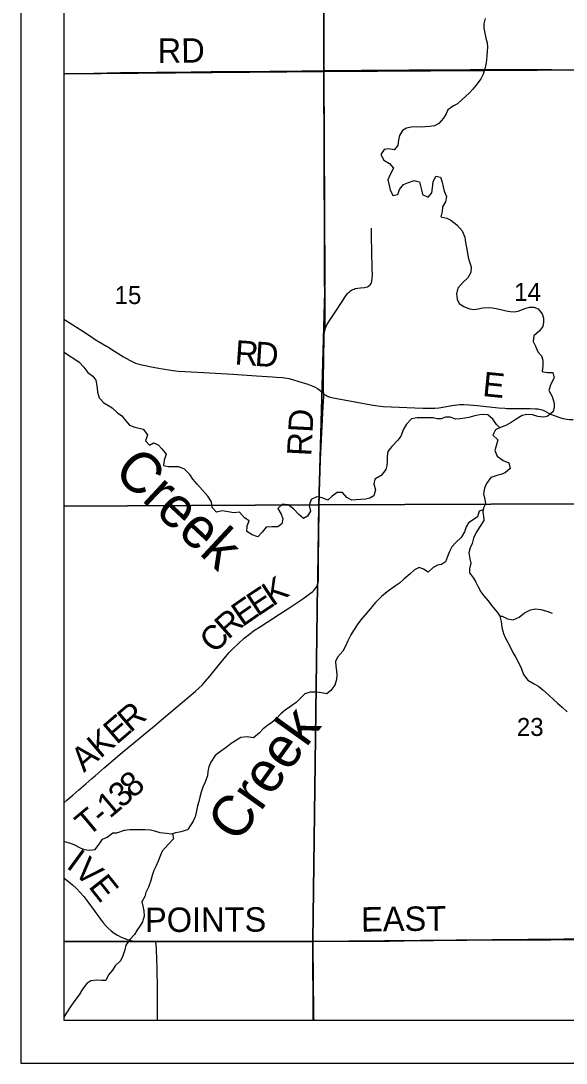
# Model space of a CAD drawing. Extents: x 0 to 70.2, y 0 to 31.4.
# Drawn here: x 2 to 3.272, y 14 to 16.429 of the extents above; entities that cross this region are included whole.
import ezdxf

# ---------------------------------------------------------------- set-up
doc = ezdxf.new("R2010")
doc.units = 0
for name, color, linetype in [('GM_X_County_Road', 7, 'Continuous'), ('GM_X_County_Road_Text', 7, 'Continuous'), ('GM_X_Minor_River', 7, 'Continuous'), ('GM_X_Minor_River_Text', 7, 'Continuous'), ('GM_X_Section', 7, 'Continuous'), ('GM_X_Section_Text', 7, 'Continuous'), ('GM_X_State_Route', 7, 'Continuous'), ('GM_X_Township_Road', 7, 'Continuous'), ('GM_X_Township_Road_Text', 7, 'Continuous'), ('SH_Cut_Line', 7, 'Continuous'), ('SH_Data', 7, 'Continuous')]:
    doc.layers.add(name, color=color, linetype=linetype)

msp = doc.modelspace()

# ---------------------------------------------------------------- linework, layer by layer
at = {"layer": 'GM_X_County_Road'}
for points in [[(2.1, 14.4319), (2.1013, 14.431), (2.1113, 14.4235), (2.1208, 14.4154), (2.1298, 14.4067), (2.1384, 14.3977), (2.1466, 14.3882), (2.1562, 14.3761), (2.1708, 14.3559), (2.1854, 14.3358), (2.193, 14.326), (2.1991, 14.319), (2.2034, 14.3146), (2.2103, 14.3085), (2.2178, 14.303), (2.2256, 14.2981), (2.2338, 14.2938), (2.2423, 14.2901), (2.2481, 14.288), (2.254, 14.2863), (2.26, 14.285), (2.2692, 14.2839), (2.2816, 14.2834), (2.3064, 14.2833), (2.3149, 14.2834)], [(2.3149, 14.2834), (2.3996, 14.2837), (2.4431, 14.2838), (2.5053, 14.2839), (2.5861, 14.2841), (2.6576, 14.2841), (2.6808, 14.2841)], [(2.6808, 14.2841), (2.7074, 14.284), (2.8316, 14.2843), (2.8596, 14.2845), (2.8938, 14.2851), (2.9622, 14.2854), (3.0399, 14.2868), (3.1021, 14.2871), (3.1736, 14.2876), (3.2356, 14.2872), (3.3133, 14.2878), (3.3941, 14.289), (3.4376, 14.2895), (3.4749, 14.2901), (3.4936, 14.2899), (3.5035, 14.2898)]]:
    msp.add_lwpolyline(points, dxfattribs=at)
at = {"layer": 'GM_X_Minor_River'}
for points in [[(3.0825, 16.434), (3.0795, 16.4218), (3.0795, 16.4116), (3.0821, 16.3998), (3.0844, 16.3884), (3.087, 16.3771), (3.0878, 16.3676), (3.0874, 16.3581), (3.0866, 16.3463), (3.0847, 16.3308), (3.0821, 16.3168), (3.0779, 16.3046), (3.0726, 16.2936), (3.0616, 16.2788), (3.054, 16.2693), (3.0453, 16.2599), (3.0293, 16.2454), (3.0183, 16.2356), (3.0085, 16.2303), (2.996, 16.2215), (2.9914, 16.2121), (2.9853, 16.2018), (2.9747, 16.1893), (2.9645, 16.184), (2.9527, 16.1821), (2.9425, 16.1817), (2.9319, 16.1809), (2.9217, 16.1813), (2.9099, 16.1809), (2.8993, 16.1783), (2.8898, 16.1734), (2.8826, 16.1616), (2.8807, 16.151), (2.8792, 16.1385), (2.8704, 16.1278), (2.8579, 16.1305), (2.8473, 16.1286), (2.8394, 16.1168), (2.8462, 16.1036), (2.8594, 16.096), (2.8693, 16.085), (2.8609, 16.0709), (2.856, 16.058), (2.8587, 16.0451), (2.8613, 16.0345), (2.867, 16.022), (2.8791, 16.0243), (2.8833, 16.0357), (2.892, 16.047), (2.9041, 16.052), (2.917, 16.0562), (2.9292, 16.0535), (2.9322, 16.044), (2.9345, 16.0345), (2.9364, 16.0239), (2.9496, 16.0175), (2.9583, 16.0277), (2.9599, 16.0398), (2.9618, 16.0535), (2.9678, 16.0668), (2.9788, 16.0641), (2.9826, 16.0527), (2.9849, 16.0417), (2.9872, 16.0319), (2.9925, 16.019), (2.9902, 16.0072), (2.983, 15.9951), (2.9822, 15.9845), (2.9792, 15.9716), (2.9932, 15.9685), (3.0027, 15.9644), (3.0163, 15.953), (3.0292, 15.939), (3.0349, 15.9249), (3.0371, 15.9124), (3.0394, 15.9003), (3.0413, 15.887), (3.0428, 15.8768), (3.047, 15.8646), (3.05, 15.8551), (3.0492, 15.8419), (3.042, 15.8297), (3.031, 15.8195), (3.0189, 15.8058), (3.0158, 15.7922), (3.017, 15.78), (3.0223, 15.7702), (3.0333, 15.763), (3.0465, 15.7577), (3.0568, 15.7561), (3.0666, 15.7577), (3.0772, 15.7596), (3.0905, 15.7603), (3.1, 15.7596), (3.1125, 15.7573), (3.122, 15.755), (3.1314, 15.7531), (3.1413, 15.7512), (3.1519, 15.7508), (3.1618, 15.7531)], [(3.1618, 15.7531), (3.1754, 15.7581), (3.186, 15.7618), (3.1959, 15.7615), (3.2065, 15.7577), (3.2156, 15.7463), (3.2186, 15.7361), (3.219, 15.7266), (3.2175, 15.7167), (3.2084, 15.7053), (3.1962, 15.6947), (3.1947, 15.6814), (3.2004, 15.6708), (3.2053, 15.6575), (3.214, 15.6481), (3.2174, 15.6378), (3.2174, 15.6245), (3.2159, 15.6117), (3.2273, 15.6094), (3.2402, 15.609), (3.2432, 15.5965), (3.2348, 15.5806), (3.231, 15.5673), (3.2386, 15.5532), (3.2439, 15.5381), (3.2439, 15.5282), (3.2409, 15.5187), (3.2291, 15.5073), (3.2196, 15.5051), (3.2052, 15.507), (3.1931, 15.5108), (3.1795, 15.5115), (3.1688, 15.5089), (3.1548, 15.5005), (3.1434, 15.4929), (3.1305, 15.4861), (3.1199, 15.4815), (3.1067, 15.4755), (3.1006, 15.4633), (3.112, 15.452), (3.1085, 15.4387), (3.1055, 15.4277), (3.1104, 15.4144), (3.1248, 15.4045), (3.1381, 15.3985), (3.1407, 15.3856), (3.1294, 15.3757), (3.1195, 15.3719), (3.11, 15.3696), (3.0956, 15.3647), (3.0854, 15.3507), (3.0812, 15.3397), (3.0785, 15.3268), (3.0819, 15.3131), (3.0835, 15.3033), (3.0789, 15.2938), (3.077, 15.2835), (3.0785, 15.2741), (3.0793, 15.2646), (3.0713, 15.2513), (3.0614, 15.2365), (3.0554, 15.2236), (3.0523, 15.2111), (3.0478, 15.2005), (3.0447, 15.1887), (3.0466, 15.1751), (3.0493, 15.1652), (3.0462, 15.1519), (3.0462, 15.1421), (3.0557, 15.1303), (3.061, 15.1204), (3.0655, 15.111), (3.0724, 15.0981), (3.0796, 15.0886), (3.0894, 15.0772), (3.0985, 15.0654), (3.111, 15.051), (3.1167, 15.0415), (3.1201, 15.0287), (3.1216, 15.0154), (3.1254, 15.0013), (3.1292, 14.9915), (3.1345, 14.9816), (3.142, 14.9687), (3.147, 14.957), (3.1538, 14.9452), (3.1614, 14.9319), (3.1674, 14.9187), (3.1723, 14.9054), (3.1822, 14.8925), (3.1966, 14.8842), (3.2076, 14.8773), (3.2174, 14.8701), (3.2303, 14.8584), (3.2417, 14.8477), (3.2515, 14.839), (3.2621, 14.8295), (3.2739, 14.8189)], [(2.1, 15.6563), (2.103, 15.6548), (2.1136, 15.6479), (2.1239, 15.6415), (2.136, 15.6335), (2.147, 15.6217), (2.1565, 15.6096), (2.1679, 15.6008), (2.1748, 15.5914), (2.1778, 15.5735), (2.1786, 15.5636), (2.1828, 15.5503), (2.1934, 15.5382), (2.2029, 15.5329), (2.2128, 15.5272), (2.2257, 15.515), (2.2356, 15.5082)], [(2.2356, 15.5082), (2.2443, 15.4972), (2.2534, 15.4862), (2.2656, 15.4816), (2.2758, 15.4797), (2.2853, 15.4771), (2.2956, 15.4641), (2.291, 15.4497), (2.3001, 15.4402), (2.3096, 15.4455), (2.3206, 15.441), (2.329, 15.4311), (2.3385, 15.4186), (2.3343, 15.4053), (2.3328, 15.3924), (2.3438, 15.3905), (2.3575, 15.3905), (2.3677, 15.3901), (2.381, 15.3844)], [(3.1168, 15.4801), (3.1093, 15.4884), (3.1006, 15.5005), (3.0892, 15.5104), (3.076, 15.5111), (3.0654, 15.5096), (3.0555, 15.5073), (3.0449, 15.5043), (3.0354, 15.5028), (3.0237, 15.5016), (3.0142, 15.5005), (3.0013, 15.505), (2.9903, 15.505), (2.9801, 15.5009), (2.9706, 15.5016), (2.9611, 15.5039), (2.9243, 15.5039), (2.9107, 15.5012), (2.8989, 15.4887), (2.8925, 15.477), (2.886, 15.461), (2.8788, 15.4512), (2.8648, 15.4367), (2.8561, 15.425), (2.8538, 15.4132), (2.8538, 15.4022), (2.853, 15.3924), (2.8507, 15.3829), (2.8401, 15.3696), (2.8257, 15.3605), (2.8234, 15.3499), (2.8268, 15.3358), (2.8234, 15.3222), (2.8139, 15.3165), (2.8045, 15.3142), (2.7931, 15.3135), (2.7813, 15.3123), (2.7719, 15.3116), (2.7601, 15.318), (2.7503, 15.3294), (2.7374, 15.3294), (2.7256, 15.321), (2.7161, 15.3116), (2.7029, 15.3169), (2.69, 15.3199), (2.6767, 15.3134), (2.6725, 15.2994), (2.6756, 15.2865), (2.6687, 15.2748), (2.6589, 15.2687), (2.6483, 15.2782), (2.6354, 15.2918), (2.6233, 15.3005), (2.6104, 15.3024), (2.5994, 15.2922), (2.6073, 15.2793), (2.6107, 15.2683), (2.6088, 15.2565), (2.599, 15.2493), (2.5849, 15.2493), (2.5717, 15.2489), (2.5626, 15.2372), (2.5523, 15.2266), (2.5394, 15.2311), (2.5266, 15.2391), (2.5277, 15.252), (2.5326, 15.2637), (2.5216, 15.2706), (2.5099, 15.2835), (2.4963, 15.2823), (2.4834, 15.2842), (2.4697, 15.2869), (2.4561, 15.2838), (2.4458, 15.2948), (2.4447, 15.3077), (2.4364, 15.321), (2.4239, 15.335), (2.4121, 15.3479), (2.4011, 15.3604), (2.3943, 15.3718), (2.381, 15.3844)], [(3.0781, 15.2896), (3.069, 15.2862), (3.0645, 15.2733), (3.0546, 15.2657), (3.0436, 15.2593), (3.0387, 15.2498), (3.0341, 15.238), (3.0269, 15.2251), (3.014, 15.2134), (3.0049, 15.2031), (2.9996, 15.1921), (2.9951, 15.1804), (2.9905, 15.1678), (2.981, 15.1618), (2.9716, 15.1602), (2.9617, 15.1546), (2.9499, 15.1443), (2.9386, 15.1511), (2.9291, 15.1549), (2.9177, 15.1492), (2.9079, 15.1405), (2.8931, 15.1276), (2.8828, 15.1181), (2.8733, 15.1121), (2.8544, 15.0984), (2.8411, 15.087), (2.8267, 15.073), (2.8153, 15.0597), (2.8024, 15.0438), (2.7929, 15.0328), (2.7842, 15.0214), (2.7755, 15.0081), (2.7698, 14.9983), (2.7626, 14.9838), (2.7569, 14.9713), (2.7508, 14.9603), (2.7391, 14.9471), (2.7338, 14.9364), (2.7345, 14.9251), (2.7364, 14.9144), (2.7368, 14.9042), (2.7364, 14.8943), (2.7318, 14.8807), (2.7231, 14.8682), (2.7136, 14.8609), (2.7007, 14.8625), (2.6898, 14.8644), (2.675, 14.8647), (2.6621, 14.8602), (2.6511, 14.8499), (2.642, 14.8401), (2.6291, 14.831), (2.6166, 14.8222), (2.6063, 14.8139), (2.595, 14.8025), (2.5855, 14.7938), (2.5752, 14.787), (2.5654, 14.779), (2.5566, 14.7695), (2.5426, 14.7581), (2.5275, 14.7604), (2.5127, 14.7589), (2.5028, 14.7528), (2.4903, 14.7445), (2.4789, 14.7357), (2.4653, 14.7263), (2.4535, 14.7168), (2.4433, 14.7016), (2.4387, 14.6902), (2.4364, 14.6796), (2.4349, 14.6694), (2.4292, 14.6531), (2.4243, 14.6428), (2.4205, 14.6314), (2.4175, 14.6197), (2.4152, 14.6094), (2.4121, 14.5999), (2.4099, 14.5882), (2.4061, 14.5738), (2.4019, 14.5635), (2.389, 14.5441)], [(3.1167, 15.0415), (3.1224, 15.0412), (3.1349, 15.0351), (3.1481, 15.0328), (3.1618, 15.0393), (3.1743, 15.0495), (3.1883, 15.0564), (3.1997, 15.0583), (3.2122, 15.0571), (3.2266, 15.0533), (3.2391, 15.0488)], [(2.1, 14.5165), (2.1012, 14.5163), (2.1157, 14.5125), (2.1251, 14.5087), (2.1384, 14.5015), (2.1479, 14.4977), (2.1608, 14.4965), (2.1734, 14.498), (2.184, 14.5125), (2.1904, 14.522), (2.2014, 14.5262), (2.2143, 14.5364), (2.2242, 14.5368), (2.2421, 14.5425), (2.2538, 14.5444), (2.2637, 14.5441), (2.2755, 14.5441), (2.2895, 14.5441), (2.3024, 14.5433), (2.3119, 14.541), (2.3244, 14.5376), (2.3396, 14.5357), (2.3514, 14.5346), (2.3617, 14.5376), (2.3738, 14.5399), (2.389, 14.5441)], [(2.354, 14.5354), (2.356, 14.5224), (2.3446, 14.5103), (2.3298, 14.4943), (2.326, 14.4848), (2.3199, 14.4704), (2.315, 14.4582), (2.3104, 14.4487), (2.3066, 14.4369), (2.3029, 14.4255), (2.2979, 14.41), (2.2911, 14.3978), (2.2888, 14.3883), (2.2824, 14.3758), (2.2847, 14.3655), (2.2869, 14.3549), (2.2873, 14.3424), (2.2839, 14.3291), (2.2778, 14.3192), (2.2703, 14.3089), (2.2649, 14.2994), (2.2539, 14.2884), (2.2448, 14.2751), (2.2422, 14.2641), (2.238, 14.2504), (2.2323, 14.2382), (2.2202, 14.2268), (2.2137, 14.217), (2.2046, 14.2059), (2.1982, 14.1926), (2.1879, 14.1923), (2.1765, 14.1934), (2.1636, 14.1915), (2.1541, 14.1854), (2.1439, 14.1725), (2.1363, 14.1592), (2.1238, 14.1428), (2.1147, 14.1307), (2.1052, 14.1151), (2.1, 14.1069)]]:
    msp.add_lwpolyline(points, dxfattribs=at)
at = {"layer": 'GM_X_Section'}
for points in [[(2.7039, 17.3191), (3.7116, 17.3342), (3.7004, 16.3169), (2.7071, 16.3105)], [(2.7071, 16.3105), (3.7004, 16.3169), (3.6966, 15.3051), (2.695, 15.3009), (2.7094, 15.8251)], [(3.6966, 15.3051), (3.6837, 14.2925), (2.681, 14.2838), (2.695, 15.3009)]]:
    msp.add_lwpolyline(points, close=True, dxfattribs=at)
at = {"layer": 'GM_X_Section_Text'}
for points in [[(2.1, 18.3126), (2.1, 14.1), (2.683, 14.1), (2.6825, 14.1062), (2.6824, 14.1385), (2.6819, 14.1739), (2.6818, 14.1969), (2.6815, 14.2211), (2.6812, 14.2482), (2.6806, 14.2846), (2.6914, 15.1151), (2.6923, 15.118), (2.6927, 15.1204), (2.693, 15.1229), (2.6931, 15.1295), (2.6935, 15.1758), (2.6943, 15.2286), (2.6948, 15.2908), (2.6958, 15.3311), (2.6983, 15.4057), (2.6993, 15.4368), (2.7032, 15.5143), (2.705, 15.5422), (2.7055, 15.5515), (2.7055, 15.5553), (2.7057, 15.5609), (2.7052, 15.5638), (2.7049, 15.5824), (2.7057, 15.6508), (2.7062, 15.6818), (2.7068, 15.6974), (2.7074, 15.7036), (2.7085, 15.7085), (2.7066, 16.3132), (2.7027, 17.7825)], [(2.7027, 17.7825), (2.7066, 16.3132), (2.7085, 15.7085), (2.7074, 15.7036), (2.7068, 15.6974), (2.7062, 15.6818), (2.7057, 15.6508), (2.7049, 15.5824), (2.7052, 15.5638), (2.7057, 15.5609), (2.7055, 15.5553), (2.7055, 15.5515), (2.705, 15.5422), (2.7032, 15.5143), (2.6993, 15.4368), (2.6983, 15.4057), (2.6958, 15.3311), (2.6948, 15.2908), (2.6943, 15.2286), (2.6935, 15.1758), (2.6931, 15.1295), (2.693, 15.1229), (2.6927, 15.1204), (2.6923, 15.118), (2.6914, 15.1151), (2.6806, 14.2846), (2.6812, 14.2482), (2.6815, 14.2211), (2.6818, 14.1969), (2.6819, 14.1739), (2.6824, 14.1385), (2.6825, 14.1062), (2.683, 14.1), (6.7623, 14.1)]]:
    msp.add_lwpolyline(points, dxfattribs=at)
at = {"layer": 'GM_X_State_Route'}
for points in [[(2.1, 17.3126), (2.1, 16.3054), (2.7071, 16.3105), (2.7039, 17.3191)], [(2.1, 16.3054), (2.1, 15.2974), (2.695, 15.3009), (2.7094, 15.8251), (2.7071, 16.3105)], [(2.1, 15.2974), (2.1, 14.2833), (2.681, 14.2838), (2.695, 15.3009)], [(2.1, 14.2833), (2.1, 14.1), (2.6814, 14.1), (2.681, 14.2838)], [(2.6814, 14.1), (3.6862, 14.1), (3.6837, 14.2925), (2.681, 14.2838)]]:
    msp.add_lwpolyline(points, close=True, dxfattribs=at)
at = {"layer": 'GM_X_Township_Road'}
msp.add_line((2.6554, 16.3121), (2.7068, 16.3127), dxfattribs=at)
for points in [[(2.1, 16.3055), (2.1024, 16.3055), (2.1388, 16.3062), (2.2324, 16.308), (2.2728, 16.3085), (2.3162, 16.3089), (2.397, 16.3095), (2.4436, 16.3102), (2.4715, 16.3104), (2.5802, 16.3113), (2.6051, 16.3115), (2.6554, 16.3121)], [(2.7068, 16.3127), (2.7169, 16.3128), (2.7945, 16.3133), (2.8314, 16.3136), (2.8625, 16.3138), (2.905, 16.3143), (2.9608, 16.3144), (3.0104, 16.3147), (3.0477, 16.3149), (3.1627, 16.3154), (3.2032, 16.3156), (3.238, 16.3151), (3.2654, 16.3147), (3.345, 16.314), (3.35, 16.3138), (3.3558, 16.3133), (3.363, 16.3114)], [(2.7087, 15.7079), (2.709, 15.7091), (2.7111, 15.7149), (2.7138, 15.7205), (2.7186, 15.7285), (2.7341, 15.7518), (2.7581, 15.7881), (2.762, 15.793), (2.7641, 15.7953), (2.7663, 15.7974), (2.7687, 15.7993), (2.7713, 15.801), (2.7741, 15.8025), (2.7769, 15.8037), (2.7799, 15.8046), (2.7859, 15.8059), (2.7921, 15.8066), (2.8011, 15.8076), (2.8044, 15.8079), (2.8085, 15.8091), (2.8106, 15.8101), (2.8149, 15.8135), (2.8173, 15.8178), (2.8185, 15.8215), (2.8196, 15.8378), (2.8189, 15.8495), (2.8187, 15.8929), (2.8178, 15.9241), (2.8173, 15.9459)], [(2.1, 15.7335), (2.1125, 15.7259), (2.1443, 15.7057), (2.1648, 15.6922), (2.1737, 15.6865), (2.1995, 15.6708), (2.2027, 15.6693), (2.2187, 15.6591), (2.2397, 15.6458), (2.2531, 15.6379), (2.2614, 15.6337), (2.2671, 15.6313), (2.273, 15.6293), (2.2819, 15.6269), (2.3124, 15.6209), (2.3399, 15.6159), (2.3552, 15.6137), (2.3676, 15.6125), (2.4265, 15.6089), (2.4947, 15.6053), (2.5495, 15.6014), (2.587, 15.5991), (2.595, 15.5987), (2.6098, 15.5976), (2.6153, 15.597), (2.6245, 15.5953), (2.6335, 15.5931), (2.6484, 15.5886), (2.669, 15.5817), (2.6807, 15.5776), (2.6863, 15.575), (2.6917, 15.572), (2.6968, 15.5684), (2.7016, 15.5645), (2.7059, 15.5603)], [(2.7059, 15.5603), (2.7054, 15.5633), (2.7052, 15.5819), (2.7059, 15.6502), (2.7064, 15.6813), (2.707, 15.6968), (2.7077, 15.703), (2.7087, 15.7079)], [(2.6919, 15.1155), (2.6925, 15.1174), (2.6929, 15.1199), (2.6932, 15.1224), (2.6934, 15.1289), (2.6937, 15.1753), (2.6945, 15.2281), (2.695, 15.2902), (2.696, 15.3306), (2.6985, 15.4051), (2.6996, 15.4362), (2.7035, 15.5138), (2.7052, 15.5417), (2.7057, 15.551), (2.7057, 15.5548), (2.7059, 15.5603)], [(2.7059, 15.5603), (2.7083, 15.558), (2.7108, 15.5562), (2.7135, 15.5546), (2.7163, 15.5533), (2.7192, 15.5523), (2.7222, 15.5514), (2.7282, 15.55), (2.7832, 15.5398), (2.8168, 15.5337), (2.8322, 15.5315), (2.8445, 15.5302), (2.8631, 15.529), (2.9376, 15.5262), (2.953, 15.526), (2.9654, 15.5264), (2.9746, 15.5272), (2.9838, 15.5285), (3.0051, 15.5325), (3.0113, 15.5332), (3.0237, 15.5343), (3.033, 15.5344), (3.0454, 15.5337), (3.0639, 15.532), (3.1134, 15.527), (3.1288, 15.5258), (3.133, 15.5257)], [(3.133, 15.5257), (3.1474, 15.5253), (3.1878, 15.5252), (3.2002, 15.5249), (3.2063, 15.5243), (3.2124, 15.523), (3.2154, 15.5221), (3.221, 15.5196), (3.232, 15.5138), (3.2375, 15.5111), (3.252, 15.5058), (3.2639, 15.5023), (3.273, 15.5002), (3.2792, 15.4997), (3.2828, 15.4998), (3.2876, 15.5)], [(2.56, 15.0185), (2.5608, 15.019), (2.6297, 15.0636), (2.6572, 15.0821), (2.6756, 15.0952), (2.6805, 15.0991), (2.6828, 15.1011), (2.685, 15.1034), (2.6883, 15.108), (2.6903, 15.1117), (2.6917, 15.1146), (2.6919, 15.1155)], [(2.1, 14.6068), (2.1073, 14.6127), (2.1213, 14.6244), (2.1354, 14.6365), (2.1514, 14.651), (2.1658, 14.663), (2.1736, 14.6694), (2.1945, 14.688), (2.2363, 14.7236), (2.3113, 14.7862), (2.3326, 14.8042), (2.4066, 14.866), (2.4159, 14.8742), (2.4225, 14.8807), (2.4308, 14.8899), (2.4408, 14.9013), (2.4602, 14.9254), (2.4777, 14.9472), (2.4858, 14.9566), (2.4943, 14.9655), (2.5075, 14.9781), (2.521, 14.99), (2.5329, 14.9997), (2.5428, 15.007), (2.56, 15.0185)], [(2.3188, 14.1), (2.3189, 14.1083), (2.3187, 14.1503), (2.3183, 14.1864), (2.3181, 14.2079), (2.3179, 14.2236), (2.3173, 14.2408), (2.316, 14.2666), (2.3149, 14.2834)], [(2.6821, 14.1864), (2.682, 14.1963), (2.6817, 14.2206), (2.6814, 14.2477), (2.6808, 14.2841)], [(2.6831, 14.1), (2.6827, 14.1057), (2.6826, 14.1379), (2.6821, 14.1734), (2.6821, 14.1864)]]:
    msp.add_lwpolyline(points, dxfattribs=at)
at = {"layer": 'SH_Cut_Line'}
msp.add_lwpolyline([(2.1, 20.9), (2.1, 14.1), (6.7623, 14.1)], dxfattribs=at)
at = {"layer": 'SH_Data'}
for p, q in [((2, 21), (2, 14)), ((2.1, 20.9), (2.1, 14.1)), ((2.1, 14.1), (8.9, 14.1)), ((2.1, 14.1), (2.1, 14.1)), ((2, 14), (9, 14))]:
    msp.add_line(p, q, dxfattribs=at)

# ---------------------------------------------------------------- texts
at = {"layer": 'GM_X_County_Road_Text'}
for s, height, rotation, p in [('I', 0.0568, 323.7718, (2.1037, 14.4563)), ('V', 0.0568, 316.6797, (2.1211, 14.4437)), ('E', 0.0568, 308.3881, (2.156, 14.411)), ('POINTS', 0.05682, 0.1956, (2.2896, 14.3055)), ('EAST', 0.05682, 0.8173, (2.7936, 14.3064))]:
    msp.add_text(s, height=height, rotation=rotation, dxfattribs=at).set_placement(p)
at = {"layer": 'GM_X_Minor_River_Text'}
for rotation, p in [(317.0868, (2.2128, 15.3738)), (54.4656, (2.5058, 14.5102))]:
    msp.add_text('Creek', height=0.09473, rotation=rotation, dxfattribs=at).set_placement(p)
at = {"layer": 'GM_X_Section_Text'}
for s, p in [('15', (2.2187, 15.7687)), ('14', (3.1503, 15.776)), ('23', (3.1566, 14.7624))]:
    msp.add_text(s, height=0.04186, rotation=0, dxfattribs=at).set_placement(p)
at = {"layer": 'GM_X_Township_Road_Text'}
for s, height, rotation, p in [('RD', 0.05682, 0.4936, (2.3193, 16.3306)), ('R', 0.0568, 356.1566, (2.4977, 15.628)), ('D', 0.0568, 356.2836, (2.5444, 15.6248)), ('E', 0.0568, 354.404, (3.075, 15.5546)), ('RD', 0.05682, 87.0387, (2.6772, 15.4135)), ('K', 0.0568, 33.5882, (2.5871, 15.063)), ('E', 0.0568, 33.5142, (2.5516, 15.0395)), ('E', 0.0568, 34.7326, (2.5169, 15.0155)), ('R', 0.0568, 41.6559, (2.4834, 14.9856)), ('C', 0.0568, 47.573, (2.4531, 14.9522)), ('R', 0.0568, 40.5193, (2.2556, 14.7685)), ('E', 0.0568, 40.4805, (2.2232, 14.7409)), ('K', 0.0568, 40.4721, (2.1852, 14.7084)), ('A', 0.0568, 40.4749, (2.1472, 14.676)), ('8', 0.0568, 40.7864, (2.2613, 14.6154)), ('3', 0.0568, 41.6497, (2.2354, 14.5923)), ('1', 0.0568, 40.1905, (2.2074, 14.5687)), ('T', 0.0568, 39.957, (2.1568, 14.5262)), ('-', 0.0568, 40.0101, (2.1894, 14.5536))]:
    msp.add_text(s, height=height, rotation=rotation, dxfattribs=at).set_placement(p)

doc.saveas('drawing.dxf')
